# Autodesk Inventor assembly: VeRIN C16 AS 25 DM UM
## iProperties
Shininess: 41.0
Angle Display Precision: 2
Document Length Units: 11269
Document Angle Units: 11279
Document Time Units: 11290
Document Mass Units: 11283
Document Length Units Precision: 3
Document Angle Units Precision: 2
Created: 2002-02
Part Number: VeRIN C16 AS 25 DM UM
Catalog Web Link: www.traceparts.com
Description: Vérin double effet, type C-AS, amortissement élastique, alésage de 16mm
Vendor: ASCO JOUCOMATIC
Document SubType Name: Assemblage
Designer: Administrateur
Density: 0.0
Volumn: 0.0
Area: 0.0
PropertySet Name: Model Information
Control State: 0
Master: False
Checked Out: False
Author: Administrateur
